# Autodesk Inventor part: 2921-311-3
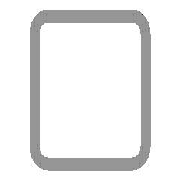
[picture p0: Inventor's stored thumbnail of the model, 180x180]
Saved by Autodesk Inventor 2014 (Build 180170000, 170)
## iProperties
IsCustomPart: 1
Company: NHTSA/VRTC
Created: 2012-02
Part Number: 2921-311-3
Material: Steel, Mild
Description: BENCH FRAME TUBE #3
Document SubType Name: Modeling
Standard: AISC
Designer: Mike Vavoorhis
Standards Organization: ANSI
Language: en-US
Size Designation: 1-1/2x1-1/2x1/8 - 25.25
Categories: <MemberInstance><Categories><Category DisplayName="Structural Shapes" InternalName="089c4875-fa83-4c05-b084-43b9cc11f5ed" Mnemonic="GRDR"><CategoryParameter Dis
Stock Number: T.S. 1 1/2 x1 1/2 x 1/8 x 641.4mm (25.25")
Density: 1 g/cm^3
Project: CHILD SIDE IMPACT SLED
Appearance: Steel
G_L: 25.250 in
Author: Dave Walker
Title: Bench Frame Tube #3
Subject: Child  Side Impact Sled
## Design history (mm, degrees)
node "Start plane"
node "End plane"
sketch "Sketch"
  geometry: L1 (-19.05, -12.7)-(-19.05, 12.7); L2 (-12.7, 19.05)-(12.7, 19.05); L3 (19.05, 12.7)-(19.05, -12.7); L4 (12.7, -19.05)-(-12.7, -19.05); L5 (-12.7, 15.875)-(12.7, 15.875); L6 (15.875, 12.7)-(15.875, -12.7); L7 (12.7, -15.875)-(-12.7, -15.875); L8 (-15.875, -12.7)-(-15.875, 12.7); L9 (0, 36.948)-(0, -36.948) reference; L10 (-23.079, 0)-(23.079, 0) reference; A1 r 6.35 centre (-12.7, -12.7) between (-19.05, -12.7) and (-12.7, -19.05); A2 r 6.35 centre (-12.7, 12.7) between (-12.7, 19.05) and (-19.05, 12.7); A3 r 6.35 centre (12.7, 12.7) between (19.05, 12.7) and (12.7, 19.05); A4 r 6.35 centre (12.7, -12.7) between (12.7, -19.05) and (19.05, -12.7); A5 r 3.175 centre (-12.7, 12.7) between (-12.7, 15.875) and (-15.875, 12.7); A6 r 3.175 centre (12.7, 12.7) between (15.875, 12.7) and (12.7, 15.875); A7 r 3.175 centre (12.7, -12.7) between (12.7, -15.875) and (15.875, -12.7); A8 r 3.175 centre (-12.7, -12.7) between (-15.875, -12.7) and (-12.7, -15.875)
  constraints: 16 end point, 16 point on circle, 8 centre point, 8 tangent, 4 parallel, 3 equal radius, 2 perpendicular, 7 other
  dimensions: "d10" = 38.1 distance between parallel lines of L2 L4 (= G_H); "d11" = 38.1 distance between parallel lines of L1 L3 (= G_W); "d12" = 3.175 distance between parallel lines of L3 L6 (= G_T); "d15" = 19.05 distance between parallel lines of L2 L10 (= 0.5 x d10); "d16" = 19.05 distance between parallel lines of L9 L3 (= 0.5 x d11); "d17" = 6.35 radius of A1 (= G_IR)
extrude "Body" new body sketch "Sketch" stored distance "d3" = 641.35 (= G_L); taper "d4" = 0 deg
node "Driven Length"
  sketch "Sketch3"
    geometry: L1 (0, 0)-(10, 0) reference
    constraints: 2 end point, 1 horizontal
  workplane "Work Plane3"
  sketch "Sketch4"
    geometry: L1 (-2, 0)-(12, 0) reference; L2 (-2, 641.35)-(12, 641.35) reference
    dimensions: "d19" = 641.35 distance between parallel lines of L1 L2 (derived)
sketch "Sketch5"
  geometry: L1 (641.35, -6.35)-(0, -6.35) reference; L2 (641.35, 31.75)-(0, 31.75) reference; L3 (0, -6.35)-(104.679, 31.75); L4 (104.679, 31.75)-(0, 31.75); L5 (0, 31.75)-(0, -6.35); 1 further point
  constraints: 6 end point, 1 collinear, 1 perpendicular, 1 point on line
  dimensions: "d20" = 20 deg angle of L1 L3
extrude "Extrusion2" cut sketch "Sketch5" stored distance "d21" = 25.4; taper "d22" = 0 deg
body "Solid1"
other parameters: "G_W" = 38.1 [user parameter; used in 1 equation term], "G_H" = 38.1 [user parameter; used in 1 equation term], "G_T" = 3.175 [user parameter; used in 1 equation term], "G_IR" = 6.35 [user parameter; used in 1 equation term], "G_L" = 641.35 (= d19) [user parameter; used in 1 equation term], "G_OFFSET_START" = 0 [user parameter; used in 1 equation term], "G_OFFSET_END" = 0 [user parameter; used in 1 equation term], "d13" = 0 (computed from G_OFFSET_START), "d14" = 641.35 (= G_OFFSET_END + B_L), "B_L" = 641.35 [user parameter; used in 1 equation term], "d18" = 90 deg
